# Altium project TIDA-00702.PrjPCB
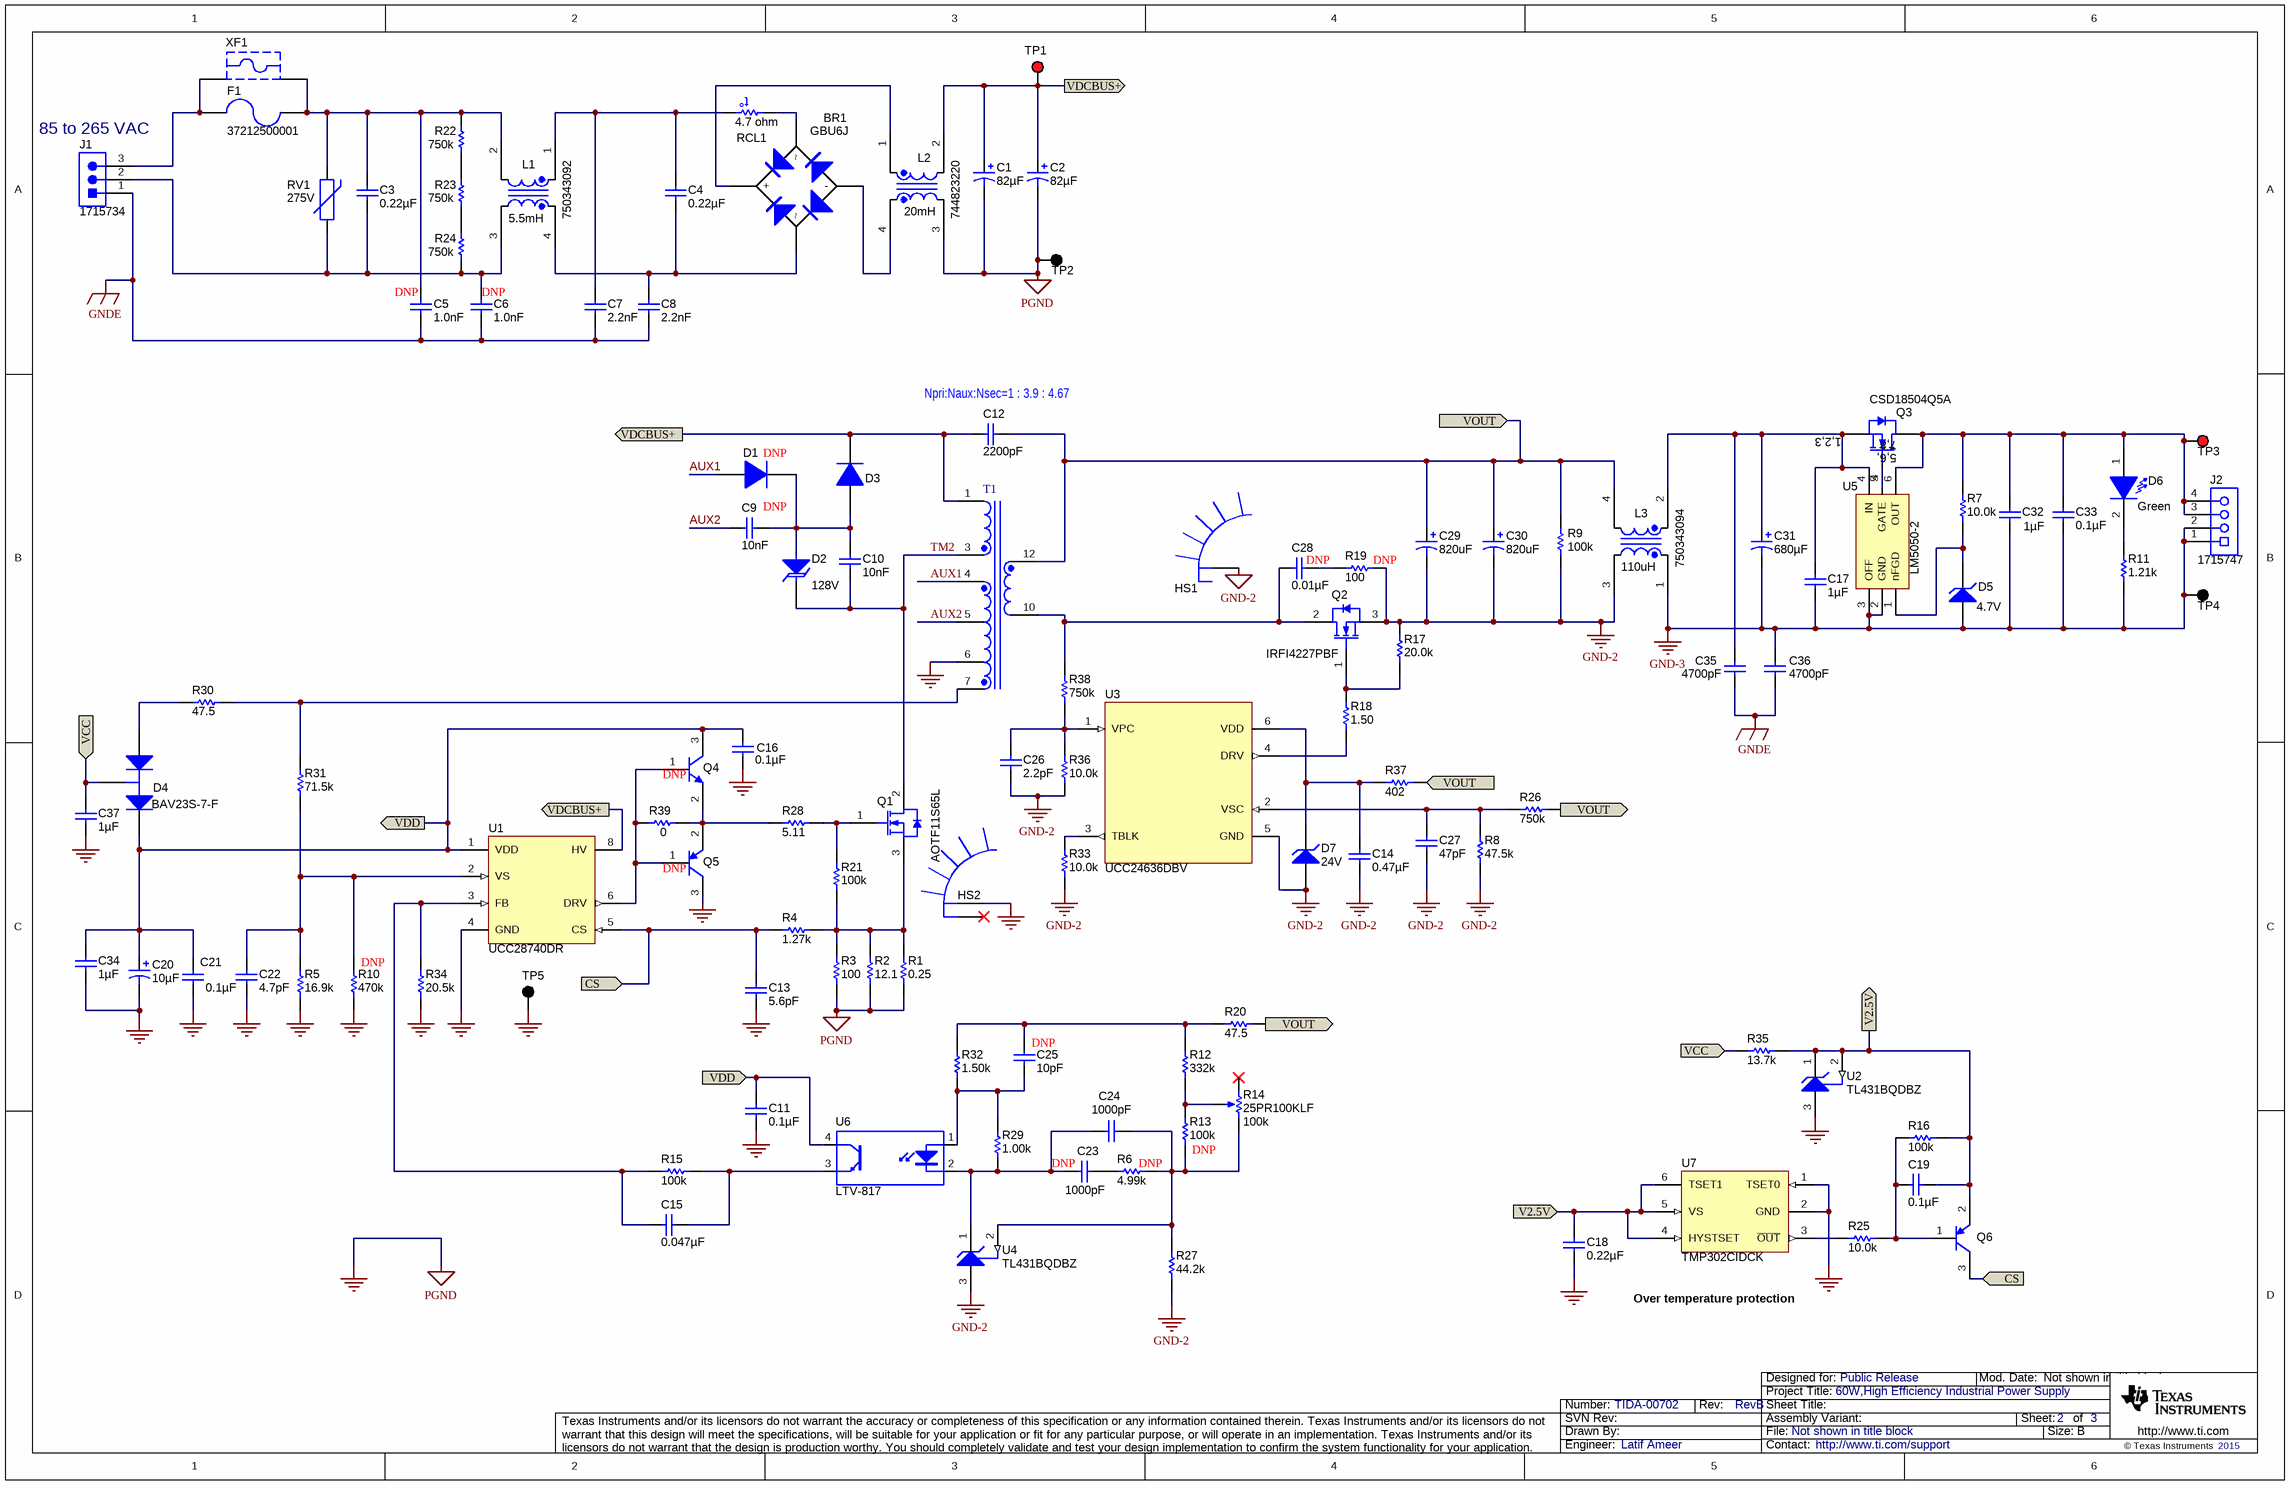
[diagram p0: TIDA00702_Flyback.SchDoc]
CopyrightYear: 2015; PCB_Layout: Manjunatha T N; PCB_Rev: RevB; PRJ_Customer: Public Release; PRJ_Engineer: Latif Ameer; PRJ_Number: TIDA-00702; PRJ_Title: 60W,High Efficiency Industrial Power Supply; SCH_Rev: RevB; TechSupport: http://www.ti.com/support
2 sheets, 137 parts. Net scope: flat (ports and power ports of the same name join across sheets).
Board file: TIDA-00702-RevB.PcbDoc
Sheets:
  TIDA00702_Flyback.SchDoc
  Hardware_ANSI-B.SchDoc

## Sheet TIDA00702_Flyback.SchDoc
size 431 x 279 mm; Date: Not shown in title block; ApprovedBy: Not shown in title block; CheckedBy: Not shown in title block; Author: Not shown in title block; CompanyName: Not shown in title block; Engineer: Not shown in title block; Organization: Not shown in title block; Address1: Not shown in title block; Address2: Not shown in title block; Address3: Not shown in title block; Address4: Not shown in title block; DocumentNumber: 1; Revision: Use project parameter SCH_Rev; SheetNumber: 2; SheetTotal: 3; PageSetup: Record=PageOptions¦CenterHorizontal=True¦CenterVertical=True¦PrintScale=1.00¦XCorrection=1.00¦YCorrection=1.00¦PrintKind=0¦BorderSize=5000000¦LeftOffset=0¦BottomOffset=0¦Orientation=2¦PaperLength=1000¦PaperWidth=1000¦Scale=100¦PaperSource=15¦PrintQuality=600¦MediaType=1¦DitherType=10¦PaperKind=Letter¦PrintScaleMode=1

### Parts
BR1  GBU6J  [GBU]
C1  ValueDisplayed: 82µF  [CAPPRD750W80D1800H3150]  (hidden comment: UCY2W820MHD6)
C2  ValueDisplayed: 82µF  [CAPPRD750W80D1800H3150]  (hidden comment: UCY2W820MHD6)
C3  ValueDisplayed: 0.22µF  [B32922_12.5mm]  (hidden comment: B32922C3224M)
C4  ValueDisplayed: 0.22µF  [B32922_12.5mm]  (hidden comment: B32922C3224M)
C5  ValueDisplayed: 1.0nF  [E_900x700x900]  (hidden comment: C907U102MYVDBA7317)
C6  ValueDisplayed: 1.0nF  [E_900x700x900]  (hidden comment: C907U102MYVDBA7317)
C7  ValueDisplayed: 2.2nF  [E_900x700x900]  (hidden comment: CS80ZU2GA222MYNKA)
C8  ValueDisplayed: 2.2nF  [E_900x700x900]  (hidden comment: CS80ZU2GA222MYNKA)
C9  ValueDisplayed: 10nF  [B32529_450x950x730]  (hidden comment: B32529C8103K)
C10  ValueDisplayed: 10nF  [B32529_450x950x730]  (hidden comment: B32529C8103K)
C11  ValueDisplayed: 0.1µF  [0603]  (hidden comment: C1608X7R1H104K)
C12  ValueDisplayed: 2200pF  [E_900x700x900]  (hidden comment: CS80ZU2GA222MYNKA)
C13  ValueDisplayed: 5.6pF  [0603]  (hidden comment: 06035A5R6CAT2A)
C14  ValueDisplayed: 0.47µF  [0805_HV]  (hidden comment: GRM21BR71H474KA88L)
C15  ValueDisplayed: 0.047µF  [0603]  (hidden comment: C1608X7R1H473K)
C16  ValueDisplayed: 0.1µF  [0603]  (hidden comment: C1608X7R1H104K)
C17  ValueDisplayed: 1µF  [0603]  (hidden comment: GRM188R61H105KAALD)
C18  ValueDisplayed: 0.22µF  [0603]  (hidden comment: C1608X7R1C224K)
C19  ValueDisplayed: 0.1µF  [0603]  (hidden comment: GRM188R61C104KA01D)
C20  ValueDisplayed: 10µF  [FC_400x1100]  (hidden comment: UVR1H100MDD6TP)
C21  ValueDisplayed: 0.1µF  [0603]  (hidden comment: C1608X7R1H104K)
C22  ValueDisplayed: 4.7pF  [0603]  (hidden comment: 06035A4R7CAT2A)
C23  ValueDisplayed: 1000pF  [0603]  (hidden comment: C1608C0G1H102J)
C24  ValueDisplayed: 1000pF  [0603]  (hidden comment: C1608C0G1H102J)
C25  ValueDisplayed: 10pF  [0603]  (hidden comment: 06035A100JAT2A)
C26  ValueDisplayed: 2.2pF  [0603]  (hidden comment: 06035A2R2CAT2A)
C27  ValueDisplayed: 47pF  [0603]  (hidden comment: 06035A470JAT2A)
C28  ValueDisplayed: 0.01µF  [0805_HV]  (hidden comment: C2012X7R2E103K)
C29  ValueDisplayed: 820uF  [CAPPR5-10X20]  (hidden comment: EEU-FR1V821L)
C30  ValueDisplayed: 820uF  [CAPPR5-10X20]  (hidden comment: EEU-FR1V821L)
C31  ValueDisplayed: 680µF  [CAPPR5-10X20]  (hidden comment: EEU-FR1V681)
C32  ValueDisplayed: 1µF  [1206]  (hidden comment: C3216X7R1H105K)
C33  ValueDisplayed: 0.1µF  [1206]  (hidden comment: C1206C104J5RACTU)
C34  ValueDisplayed: 1µF  [1206]  (hidden comment: C3216X7R1H105K)
C35  ValueDisplayed: 4700pF  [CAPRD750W60D750H1050]  (hidden comment: VY2472M49Y5US63V7)
C36  ValueDisplayed: 4700pF  [CAPRD750W60D750H1050]  (hidden comment: VY2472M49Y5US63V7)
C37  ValueDisplayed: 1µF  [1206]  (hidden comment: C3216X7R1H105K)
D1  BYG21M-E3/TR  [SMA]  (value not drawn)
D2  value 128V  [DO-201AD_Vert]  (hidden comment: 1.5KE150A)
D3  BYG21M-E3/TR  [SMA]  (value not drawn)
D4  BAV23S-7-F  [SOT-23]
D5  value 4.7V  [SOD-523]  (hidden comment: BZT52C4V7T-7)
D6  value Green  [LED_HLMP1523]  (hidden comment: HLMP1503)
D7  value 24V  [SOD-123]  (hidden comment: MMSZ5252B-7-F)
F1  37212500001  [FUSE_372]
HS1  V7237C  [HEATSINK_V7237C]  (value not drawn)
HS2  593002B00000G  [HEATSINK_593002B03400G]  (value not drawn)
J1  1715734  [Phoenix_1715734]
J2  1715747  [Phoenix_1715747]
L1  750343092  ValueDisplayed: 5.5mH  [750311982]
L2  744823220  ValueDisplayed: 20mH  [IND_WE-CMB_M]
L3  750343094  ValueDisplayed: 110uH  [IND_750343094]
Q1  AOTF11S65L  [TO-220_FullPAK_Offset]
Q2  IRFI4227PBF  [TO-220AB]
Q3  CSD18504Q5A  [TRANS_NexFET_Q5A]
Q4  MMBT4401WT1G  [SOT-323]  (value not drawn)
Q5  MMBT4403WT1G  [SOT-323]  (value not drawn)
Q6  MMBT4403WT1G  [SOT-323]  (value not drawn)
R1  ValueDisplayed: 0.25  [2010]  (hidden comment: CSRN2010FKR250)
R2  ValueDisplayed: 12.1  [2010]  (hidden comment: CRCW201012R1FKEF)
R3  ValueDisplayed: 100  [1206]  (hidden comment: CRCW1206100RFKEA)
R4  ValueDisplayed: 1.27k  [0603]  (hidden comment: CRCW06031K27FKEA)
R5  ValueDisplayed: 16.9k  [0603]  (hidden comment: CRCW060316K9FKEA)
R6  ValueDisplayed: 4.99k  [0603]  (hidden comment: CRCW06034K99FKEA)
R7  ValueDisplayed: 10.0k  [0603]  (hidden comment: CRCW060310K0FKEA)
R8  ValueDisplayed: 47.5k  [0603]  (hidden comment: CRCW060347K5FKEA)
R9  ValueDisplayed: 100k  [1206]  (hidden comment: CRCW1206100KFKEA)
R10  ValueDisplayed: 470k  [0603]  (hidden comment: RC0603FR-07470KL)
R11  ValueDisplayed: 1.21k  [0603]  (hidden comment: CRCW06031K21FKEA)
R12  ValueDisplayed: 332k  [0603]  (hidden comment: CRCW0603332KFKEA)
R13  ValueDisplayed: 100k  [0603]  (hidden comment: CRCW0603100KFKEA)
R14  25PR100KLF  value 100k  [POT_25PXXXXXX]
R15  ValueDisplayed: 100k  [0603]  (hidden comment: CRCW0603100KFKEA)
R16  ValueDisplayed: 100k  [0603]  (hidden comment: CRCW0603100KFKEA)
R17  ValueDisplayed: 20.0k  [0603]  (hidden comment: CRCW060320K0FKEA)
R18  ValueDisplayed: 1.50  [0603]  (hidden comment: CRCW06031R50FKEA)
R19  ValueDisplayed: 100  [1206]  (hidden comment: CRCW1206100RFKEA)
R20  ValueDisplayed: 47.5  [0603]  (hidden comment: CRCW060347R5FKEA)
R21  ValueDisplayed: 100k  [0603]  (hidden comment: CRCW0603100KFKEA)
R22  ValueDisplayed: 750k  [1206]  (hidden comment: CRCW1206750KFKEA)
R23  ValueDisplayed: 750k  [1206]  (hidden comment: CRCW1206750KFKEA)
R24  ValueDisplayed: 750k  [1206]  (hidden comment: CRCW1206750KFKEA)
R25  ValueDisplayed: 10.0k  [0603]  (hidden comment: CRCW060310K0FKEA)
R26  ValueDisplayed: 750k  [0603]  (hidden comment: CRCW0603750KFKEA)
R27  ValueDisplayed: 44.2k  [0603]  (hidden comment: CRCW060344K2FKEA)
R28  ValueDisplayed: 5.11  [0603]  (hidden comment: CRCW06035R11FKEA)
R29  ValueDisplayed: 1.00k  [0603]  (hidden comment: CRCW06031K00FKEA)
R30  ValueDisplayed: 47.5  [0805_HV]  (hidden comment: CRCW080547R5FKEA)
R31  ValueDisplayed: 71.5k  [0603]  (hidden comment: CRCW060371K5FKEA)
R32  ValueDisplayed: 1.50k  [0603]  (hidden comment: CRCW06031K50FKEA)
R33  ValueDisplayed: 10.0k  [0603]  (hidden comment: CRCW060310K0FKEA)
R34  ValueDisplayed: 20.5k  [0603]  (hidden comment: CRCW060320K5FKEA)
R35  ValueDisplayed: 13.7k  [0603]  (hidden comment: CRCW060313K7FKEA)
R36  ValueDisplayed: 10.0k  [0603]  (hidden comment: CRCW060310K0FKEA)
R37  ValueDisplayed: 402  [0603]  (hidden comment: CRCW0603402RFKEA)
R38  ValueDisplayed: 750k  [0603]  (hidden comment: CRCW0603750KFKEA)
R39  ValueDisplayed: 0  [0603]  (hidden comment: CRCW06030000Z0EA)
RCL1  value 4.7 ohm  [THERM_B57236S0]  (hidden comment: B57236S479M)
RV1  value 275V  [VAR_S10K275E2]  (hidden comment: S10K275E2)
T1  (no value)  [Trans_FBtrans00702]
TP1  5000  [Keystone5000]  (value not drawn)
TP2  5001  [Keystone5001]  (value not drawn)
TP3  5000  [Keystone5000]  (value not drawn)
TP4  5001  [Keystone5001]  (value not drawn)
TP5  5001  [Keystone5001]  (value not drawn)
U1  UCC28740DR  [D0007A_N]
U2  TL431BQDBZ  [DBZ0003A_L]
U3  UCC24636DBV  [DBV0006A_N]
U4  TL431BQDBZ  [DBZ0003A_L]
U5  LM5050-2  [tsop-6]
U6  LTV-817  [DIP762W60P254L460H350Q4B]
U7  TMP302CIDCK  [DCK0006A_N]
XF1  56000001009  [FuseHolder_560000010]  (value not drawn)

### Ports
CS (in), V2.5V (in), V2.5V (out), VCC (in), VDCBUS+, VDD (in), VDD (out), VOUT (in)

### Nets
GND: C1.2(-) C2.2(-) C11.2 C13.2 C16.2 C18.2 C20.2(-) C21.2 C22.2 C34.2 C37.2 HS2.1 L2.3 Q5.3(C) R1.1 R2.2 R3.1 R5.2 R10.1 R34.1 T1.6 TP2.1 TP5.1 U1.4(GND) U2.3(ANODE) U7.1(TSET0) U7.2(GND)  [also labelled PGND]
GND-2: C14.1 C26.2 C27.1 C29.2(-) C30.2(-) D7.2(A) HS1.1 L3.3 Q2.3(S) R8.2 R9.1 R17.2 R19.2 R27.2 R33.2 R36.1 U3.5(GND) U4.3(ANODE)
GND-3: C17.2 C31.2(-) C32.2 C33.2 C36.1 D5.2(A) J2.1 J2.2 L3.1 R11.1 TP4.1 U5.2(GND) U5.3(OFF)
GNDE: C5.2 C6.2 C7.2 C8.2 C35.2 C36.2 J1.1
AUX1: D1.2(A) T1.4
AUX2: C9.2 T1.5
CS: C13.1 Q6.3(C) R4.1 U1.5(CS) ; port CS
TM2: C10.2 D2.1(K) Q1.2(D) T1.3
V2.5V: C18.1 C19.2 Q6.2(E) R16.2 R35.2 U2.1(CATHODE) U2.2(REF) U7.4(HYSTSET) U7.5(VS) U7.6(TSET1) ; port V2.5V
VCC: C37.1 D4.3(C) R35.1 ; port VCC
VDCBUS+: C1.1(+) C2.1(+) C12.1 D3.1(K) L2.2 T1.1 TP1.1 U1.8(HV) ; port VDCBUS+
VDD: C11.1 C16.1 C20.1(+) C21.1 C34.1 D4.2(K) Q4.3(C) U1.1(VDD) U6.4(C) ; port VDD
VOUT: C12.2 C29.1(+) C30.1(+) L3.4 R9.2 R20.1 R26.1 R37.1 T1.12 ; port VOUT
NetBR1_1: BR1.1(+) L2.1
NetBR1_2: BR1.2 C4.2 C8.1 L1.4
NetBR1_3: BR1.3 RCL1.1
NetBR1_4: BR1.4(-) L2.4
NetC3_1: C3.1 C5.1 F1.1 L1.2 R22.1 RV1.2 XF1.1
NetC3_2: C3.2 C6.1 J1.2 L1.3 R24.2 RV1.1
NetC4_1: C4.1 C7.1 L1.1 RCL1.2
NetC9_1: C9.1 C10.1 D1.1(K) D2.2(A) D3.2(A)
NetC14_2: C14.2 D7.1(K) R37.2 U3.6(VDD)
NetC15_1: C15.1 R15.2 R34.2 U1.3(FB)
NetC15_2: C15.2 R15.1 U6.3(E)
NetC17_1: C17.1 C31.1(+) C35.1 L3.2 Q3.1(S) Q3.2(S) Q3.3(S) U5.4(IN)
NetC19_1: C19.1 Q6.1(B) R16.1 R25.2
NetC22_1: C22.1 R5.1 R10.2 R31.1 U1.2(VS)
NetC23_1: C23.1 C24.1 R29.1 U4.1(CATHODE) U6.2(K)
NetC23_2: C23.2 R6.2
NetC24_2: C24.2 R6.1 R13.1 R14.3(CW) R27.1 U4.2(REF)
NetC25_1: C25.1 R12.2 R20.2 R32.1
NetC25_2: C25.2 R29.2 R32.2 U6.1(A)
NetC26_1: C26.1 R36.2 R38.1 U3.1(VPC)
NetC27_2: C27.2 R8.1 R26.2 U3.2(VSC)
NetC28_1: C28.1 R19.1
NetC28_2: C28.2 Q2.2(D) R38.2 T1.10
NetC32_1: C32.1 C33.1 D6.1(A) J2.3 J2.4 Q3.5(D) Q3.6(D) Q3.7(D) Q3.8(D) Q3.9(D) R7.1 TP3.1 U5.6(OUT)
NetD4_1: D4.1(A) R30.2
NetD5_1: D5.1(K) R7.2 U5.1(nFGD)
NetD6_2: D6.2(K) R11.2
NetF1_2: F1.2 J1.3 XF1.2
NetQ1_1: Q1.1(G) R21.2 R28.2
NetQ1_3: Q1.3(S) R1.2 R2.1 R3.2 R4.2 R21.1
NetQ2_1: Q2.1(G) R17.1 R18.2
NetQ3_4: Q3.4(G) U5.5(GATE)
NetQ4_1: Q4.1(B) Q5.1(B) R39.1 U1.6(DRV)
NetQ4_2: Q4.2(E) Q5.2(E) R28.1 R39.2
NetR12_1: R12.1 R13.2 R14.2(WIPER)
NetR18_1: R18.1 U3.4(DRV)
NetR22_2: R22.2 R23.1
NetR23_2: R23.2 R24.1
NetR25_1: R25.1 U7.3(~{OUT})
NetR30_1: R30.1 R31.2 T1.7
NetR33_1: R33.1 U3.3(TBLK)

Not connected (* = marked no-connect by the designer): HS2 2*; R14 1(CCW)*

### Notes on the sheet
- (near J1) 85 to 265 VAC
- (near C5) DNP
- (near C6) DNP
- (near C12) Npri:Naux:Nsec=1 : 3.9 : 4.67
- (near D1) DNP
- (near C9) DNP
- (near C28) DNP
- (near R19) DNP
- (near Q4) DNP
- (near Q5) DNP
- (near R10) DNP
- (near C25) DNP
- (near C23) DNP
- (near R6) DNP
- (near R13) DNP
- Over temperature protection

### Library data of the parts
BR1 = GBU4A-BP: RECT BRIDGE GPP 6A 600V GBU; Manufacturer: Micro Commercial Components; CompType: Diode; U/M: EA; Vf_V: 0.95; Io_A: 4; Vr_V: 50; Value2: 50V; TJmax_C: 150; RJC_CperW: 2.2
C1 C2 = EEUED2E820S: CAP ALUM 82UF 20% 450V RADIAL; Polarized: Y; CompType: Capacitor; U/M: EA; Cap_F: 0.000082; Tolerance_%: 20; VDC_V: 450; IRMS_A: 730mA; TaMin_C: -25; TaMax_C: 105; AC_Derating: 0.3
C3 C4 = B32922C3224M: CAP, Film, 0.22 µF, 630 V, +/- 20%, TH; Manufacturer: TDK; Polarized: N; CompType: Capacitor; Value: 0.22uF; U/M: EA; Cap_F: 0.00000022; Tolerance_%: 20; Value1: Unknown; VDC_V: 630; Value2: 630V; TaMax_C: 110
C5 C6 = DE6E3KJ222MN3A: CAP CER 1000PF 400VAC Y5V RADIAL; Manufacturer: Kemet; Polarized: N; CompType: Capacitor; Value: 1.0nF; U/M: EA; Cap_F: 0.0000000022; Tolerance_%: 20; Value1: Unknown; VDC_V: 300; Value2: 400V; TempCo: E; TaMin_C: -40; TaMax_C: 125
C7 C8 C12 = DE6E3KJ222MN3A: CAP CER 2200PF 300VAC 20% RADIAL; Manufacturer: TDK Corporation; Polarized: N; CompType: Capacitor; Value: 2.2nF; U/M: EA; Cap_F: 0.0000000022; Tolerance_%: 20; Value1: Unknown; VDC_V: 300; Value2: 300V; TempCo: E; TaMin_C: -40; TaMax_C: 125
C9 C10 = B32529C6223J: CAP FILM 10000PF 10% 630VDC RAD; Manufacturer: EPCOS (TDK); Polarized: N; CompType: Capacitor; Value: 10nF; U/M: EA; Tolerance_%: 5; Value1: Unknown; VDC_V: 630; Value2: 630V; TaMin_C: -55; TaMax_C: 125
C11 C16 C21 = C1608X7R1H104K: CAP, CERM, 0.1 µF, 50 V, +/- 10%, X7R, 0603; Manufacturer: TDK; Polarized: N; CompType: Capacitor; Value: 0.1uF; U/M: EA; Cap_F: 0.0000001; Tolerance_%: 10; ESR_ohm: 0.017; Value1: 0.017 ohm; VDC_V: 50; Value2: 50V; TaMin_C: -55; TaMax_C: 125
C13 = 06035A5R6CAT2A: CAP, CERM, 5.6 pF, 50 V, +/- 5%, C0G/NP0, 0603; Manufacturer: AVX; Polarized: N; CompType: Capacitor; Value: 5.6pF; U/M: EA; Cap_F: 0.0000000000056; Tolerance_%: 5; ESR_ohm: 0.568; Value1: 0.568 ohm; VDC_V: 50; Value2: 50V; TaMin_C: -55; TaMax_C: 125
C14 = GRM21BR71H474KA88L: CAP, CERM, 0.47 µF, 50 V, +/- 10%, X7R, 0805; Manufacturer: MuRata; Polarized: N; CompType: Capacitor; Value: 0.47uF; U/M: EA; Cap_F: 0.00000047; Tolerance_%: 10; Value1: Unknown; VDC_V: 50; Value2: 50V; TaMin_C: -55; TaMax_C: 125; Cap_Case: 0805
C15 = C1608X7R1H473K: CAP, CERM, 0.047 µF, 50 V, +/- 10%, X7R, 0603; Manufacturer: TDK; Polarized: N; CompType: Capacitor; Value: 0.047uF; U/M: EA; Cap_F: 0.000000047; Tolerance_%: 10; ESR_ohm: 0.0234; Value1: 0.0234 ohm; VDC_V: 50; Value2: 50V; TaMin_C: -55; TaMax_C: 125
C17 = GRM188R61H105KAALD: CAP, CERM, 1 µF, 50 V, +/- 10%, X5R, 0603; Manufacturer: MuRata; Polarized: N; CompType: Capacitor; Value: 1uF; U/M: EA; Cap_F: 0.000001; Tolerance_%: 10; Value1: Unknown; VDC_V: 50; Value2: 50V; TaMin_C: -55; TaMax_C: 85
C18 = C1608X7R1C224K: CAP, CERM, 0.22 µF, 16 V, +/- 10%, X7R, 0603; Manufacturer: TDK; Polarized: N; CompType: Capacitor; Value: 0.22uF; U/M: EA; Cap_F: 0.00000022; Tolerance_%: 10; ESR_ohm: 0.0125; Value1: 0.0125 ohm; VDC_V: 16; Value2: 16V; TaMin_C: -55; TaMax_C: 125
C19 = GRM188R61C104KA01D: CAP, CERM, 0.1 µF, 16 V, +/- 10%, X5R, 0603; Manufacturer: MuRata; Polarized: N; CompType: Capacitor; Value: 0.1uF; U/M: EA; Cap_F: 0.0000001; Tolerance_%: 10; Value1: Unknown; VDC_V: 16; Value2: 16V; TaMin_C: -55; TaMax_C: 85
C20 = EEU-FC1H100: CAP ALUM 10UF 20% 50V RADIAL; Manufacturer: Nichicon; Polarized: Y; CompType: Capacitor; U/M: EA; Cap_F: 0.00001; Tolerance_%: 20; Value1: 2.5 ohm; VDC_V: 50; ESR_ohm: 2.5; IRMS_A: 0.09; TaMin_C: -55; TaMax_C: 105; Cap_Case: 4.0x11.0
C22 = 06035A4R7CAT2A: CAP, CERM, 4.7 pF, 50 V, +/- 5%, C0G/NP0, 0603; Manufacturer: AVX; Polarized: N; CompType: Capacitor; Value: 4.7pF; U/M: EA; Cap_F: 0.0000000000047; Tolerance_%: 5; ESR_ohm: 0.633; Value1: 0.633 ohm; VDC_V: 50; Value2: 50V; TaMin_C: -55; TaMax_C: 125
C23 C24 = C1608C0G1H102J: CAP, CERM, 1000 pF, 50 V, +/- 5%, C0G/NP0, 0603; Manufacturer: TDK; Polarized: N; CompType: Capacitor; Value: 1000pF; U/M: EA; Cap_F: 0.000000001; Tolerance_%: 5; ESR_ohm: 0.0563; Value1: 0.0563 ohm; VDC_V: 50; Value2: 50V; TaMin_C: -55; TaMax_C: 125
C25 = 06035A100JAT2A: CAP, CERM, 10 pF, 50 V, +/- 5%, C0G/NP0, 0603; Manufacturer: AVX; Polarized: N; CompType: Capacitor; Value: 10pF; U/M: EA; Cap_F: 0.00000000001; Tolerance_%: 5; ESR_ohm: 0.403; Value1: 0.403 ohm; VDC_V: 50; Value2: 50V; TaMin_C: -55; TaMax_C: 125
C26 = 06035A2R2CAT2A: CAP, CERM, 2.2 pF, 50 V, +/- 11%, C0G/NP0, 0603; Manufacturer: AVX; Polarized: N; CompType: Capacitor; Value: 2.2pF; U/M: EA; Cap_F: 0.0000000000022; Tolerance_%: 11; ESR_ohm: 1.033; Value1: 1.033 ohm; VDC_V: 50; Value2: 50V; TaMin_C: -55; TaMax_C: 125
C27 = 06035A470JAT2A: CAP, CERM, 47 pF, 50 V, +/- 5%, C0G/NP0, 0603; Manufacturer: AVX; Polarized: N; CompType: Capacitor; Value: 47pF; U/M: EA; Cap_F: 0.000000000047; Tolerance_%: 5; ESR_ohm: 0.174; Value1: 0.174 ohm; VDC_V: 50; Value2: 50V; TaMin_C: -55; TaMax_C: 125
C28 = C2012X7R2E103K: CAP, CERM, 0.01 µF, 250 V, +/- 10%, X7R, 0805; Manufacturer: TDK; Polarized: N; CompType: Capacitor; Value: 0.01uF; U/M: EA; Cap_F: 0.00000001; Tolerance_%: 10; ESR_ohm: 0.0681; Value1: 0.0681 ohm; VDC_V: 250; Value2: 250V; TaMin_C: -55; TaMax_C: 125; Cap_Case: 0805
C29 C30 = EEU-FR1V681: CAP ALUM 820UF 20% 35V RADIAL; Manufacturer: Panasonic; Polarized: Y; CompType: Capacitor; U/M: EA; Cap_F: 0.00082; Tolerance_%: 20; Value1: Unknown; VDC_V: 35; IRMS_A: 2.47; TaMin_C: -40; TaMax_C: 105; Cap_Case: 10x27
C31 = EEU-FR1V681: CAP, AL, 680 µF, 35 V, +/- 20%, TH; Manufacturer: Panasonic; Polarized: Y; CompType: Capacitor; Value: 680uF; U/M: EA; Cap_F: 0.00068; Tolerance_%: 20; Value1: Unknown; VDC_V: 35; Value2: 35V; IRMS_A: 2.47; TaMin_C: -40; TaMax_C: 105; Cap_Case: 10x20
C32 C34 C37 = C3216X7R1H105K: CAP, CERM, 1 µF, 50 V, +/- 10%, X7R, 1206; Manufacturer: TDK; Polarized: N; CompType: Capacitor; Value: 1uF; U/M: EA; Cap_F: 0.000001; Tolerance_%: 10; ESR_ohm: 0.01; Value1: 0.01 ohm; VDC_V: 50; Value2: 50V; IRMS_A: 3.2; TaMin_C: -55; TaMax_C: 125
C33 = C1206C104J5RACTU: CAP, CERM, 0.1 µF, 50 V, +/- 5%, X7R, 1206; Manufacturer: Kemet; Polarized: N; CompType: Capacitor; Value: 0.1uF; U/M: EA; Cap_F: 0.0000001; Tolerance_%: 5; ESR_ohm: 0.059; Value1: 0.059 ohm; VDC_V: 50; Value2: 50V; IRMS_A: 1.2; TaMin_C: -55; TaMax_C: 125
C35 C36 = VY2102M29Y5UG63V7: CAP CER 4700PF 440VAC Y5U RADIAL; Manufacturer: Vishay-Bccomponents; Polarized: N; CompType: Capacitor; U/M: EA; Tolerance_%: 20; Value1: Unknown; Value2: 300; TaMin_C: -40; TaMax_C: 125; Cap_Case: Radial Disc 7.5mm, ls=7.5; AEC Category: Q200
D1 D3 = BYG21M-E3/TR: Diode, Fast Rectifier, 1000 V, 1.5 A, SMA; Manufacturer: Vishay-Semiconductor; U/M: EA; Vf_V: 1.6; Value: 1000V; Value1: 1.5A; Value2: 1.6V; Io_A: 1.5; Vr_V: 1000; TJmax_C: 150
D2 = SMCJ100A: TVS DIODE 128VWM 207VC AXIAL; Manufacturer: Littelfuse; U/M: EA; Power_W: 1500; Vr_V: 100; Value1: 1500W; RJA_CperW: 75
D4 = BAV23S-7-F: Diode, Switching, 200 V, 0.4 A, SOT-23; Manufacturer: Diodes Inc.; U/M: EA; Vf_V: 1.25; Value: 200V; Value1: 0.4A; Value2: 1.25V; Io_A: 0.4; Vr_V: 200; TJmax_C: 150; RJC_CperW: 357
D5 = BZT52C4V7T-7: Diode, Zener, 4.7 V, 300 mW, SOD-523; Manufacturer: Diodes Inc.; U/M: EA; SymbolCreator: a0412235; Power_W: 0.3; Vz_V: 4.7; Value1: 0.3W; RJA_CperW: 417
D6 = HLMP1523: LED SS HI EFF GREEN DIFF 3MM; Manufacturer: Everlight; Vf_V: 2.2; Value2: 2.2V; Io_A: 0.02; Tjmax_C: 100; Value1: W; U/M: EA
D7 = MMSZ5252B-7-F: Diode, Zener, 24V, 500mW, SOD-123; Manufacturer: Diodes Inc.; SymbolCreator: a0412235; U/M: EA; Power_W: 0.5; Vz_V: 24; Value1: 0.5W; RJA_CperW: 350
F1 = 37212500001: Fuse, 2.5 A, 250 V, TH; Manufacturer: Littelfuse; U/M: EA; OpeningTime_200%_max: 2; VDC_V: 250; Irating_A: 2.5; Vdrop: 0.08; Soldering_Wave_MaxTemp_C: 260; Soldering_Wave_MaxTime_s: 5
HS1 = 593002B00000G: HEATSINK TO-220 19.05X13.21MM; Manufacturer: Assmann WSW Components; SymbolCreator: a0799628; Value: 21.0°C/W
HS2 = 593002B00000G: HEATSINK TWISTED FIN TO-220 Vertical; Manufacturer: Aavid Thermalloy; SymbolCreator: a0799628; Value: 13.4°C/W
J1 = 1715734: TERM BLOCK 3POS 5.08MM, TH; Manufacturer: Phoenix Contact; SymbolCreator: a0799628; CompType: Header; U/M: EA
J2 = 1715747: Terminal Block, 5.08mm, 4x1, TH; Manufacturer: Phoenix Contact; SymbolCreator: a0411947; U/M: EA
L1 = 744823210: Coupled inductor, 7mH, 2 A, 0.045 ohm,+/-32%; Manufacturer: Wurth Elektronik; SymbolCreator: a0412235; Value: 5.5mH; Ind_H: 5.5e-3; DCR_ohm: 0.045
L2 = 744823210: Coupled inductor, 20 mH, 1.5A, 0.270 ohm, +/- 30%, TH; Manufacturer: Wurth Elektronik; SymbolCreator: a0412235; Value: 20mH; Ind_H: 20.0E-3; DCR_ohm: 0.270; Tolerance_%: 30
L3 = 744823210: Coupled inductor, 7mH, 2 A, 0.045 ohm, 3.7-7.1 mH; Manufacturer: Wurth Elektronik; SymbolCreator: a0412235; Value: 100uH; DCR_ohm: 0.045; Isat: 2; Tolerance_%: 30
Q1 = IPP50R199CP: MOSFET N-CH 650V 11A TO220F; Manufacturer: Alpha & Omega Semiconductor Inc.; Alternate Manufacturer: None; U/M: EA; ChType: N; VdsMax_V: 650; Value1: 399 mohm; Rdson45_ohm: 0; Value2: 13.2nC; QgTyp_nC: 34; Vgs_V: 20
Q2 = IRFB4410ZPBF: MOSFET N-CH 200V 26A TO-220FP; Manufacturer: International Rectifier; Alternate Manufacturer: None; U/M: EA; ChType: N; VdsMax_V: 200; Value1: 25 mOhm @ 17A, 10V; Value2: 100 nC; QgTyp_nC: 100nC at 10V; Vgs_V: 20; IdsMax_A: 97
Q3 = CSD18504Q5A: MOSFET, N-CH, 40 V, 15 A, SON 5x6mm; Manufacturer: Texas Instruments; Alternate Manufacturer: None; U/M: EA; ChType: N; Value: 40V; VdsMax_V: 40; Value1: 0.0098 ohm; Rdson45_ohm: 0.0098; Value2: 7.7 nC; QgTyp_nC: 7.7; Vgs_V: 20; IdsMax_A: 15
Q4 = CMST2222A TR, Central Semiconductor: Transistor, NPN, 40 V, 0.6 A, SOT-323; Manufacturer: ON Semiconductor; CompType: BJT; PNP: 0; NPN: 1; Vceo_V: 40; Vcesat1_V: 0.3; Value: 40 V; IcRated_A: 0.6; Value1: 0.6 A; TaMin_C: -65; TaMax_C: 150; U/M: EA
Q5 = MMBT2907A, Fairchild Semiconductor: Transistor, PNP, 40 V, 0.6 A, SOT-323; Manufacturer: ON Semiconductor; CompType: BJT; PNP: 1; NPN: 0; Vceo_V: 40; Vcesat1_V: 0.75; Value: 40 V; IcRated_A: 0.8; Value1: 0.6 A; HfeMax: 300; TaMin_C: -55; TaMax_C: 150; U/M: EA
Q6 = MMBT2907A, Fairchild Semiconductor: Transistor, PNP, 40 V, 0.6 A, SOT-323; CompType: BJT; PNP: 1; NPN: 0; Vceo_V: 40; Vcesat1_V: 0.75; Value: 40 V; IcRated_A: 0.8; Value1: 0.6 A; HfeMax: 300; TaMin_C: -55; TaMax_C: 150; U/M: EA
R1 = CSRN2010FKR250: RES, 0.25, 1%, 1 W, 2010; Manufacturer: Stackpole Electronics Inc; CompType: Resistor; Value: 0.25; Value_Code: R250; Tolerance_%: 1; Value2: 1W; TempCo: 250 ppm/C; U/M: EA
R2 = CRCW201012R1FKEF: RES, 12.1, 1%, 0.75 W, 2010; Manufacturer: Vishay-Dale; CompType: Resistor; Value: 12.1; Value_Code: 12R1; Tolerance_%: 1; Power_W: 0.75; Value2: 0.75W; VDC_V: 400; TempCo: 100 ppm/C; EIA_Code: E96; U/M: EA
R3 R19 = CRCW1206100RFKEA: RES, 100, 1%, 0.25 W, 1206; Manufacturer: Vishay-Dale; CompType: Resistor; Value: 100; Value_Code: 100R; Tolerance_%: 1; Power_W: 0.25; Value2: 0.25W; VDC_V: 200; TempCo: 100 ppm/C; EIA_Code: E96; U/M: EA
R4 = CRCW06031K27FKEA: RES, 1.27 k, 1%, 0.1 W, 0603; Manufacturer: Vishay-Dale; CompType: Resistor; Value: 1.27k; Res_ohm: 1270; Value_Code: 1k27; Tolerance_%: 1; Power_W: 0.1; Value2: 0.1W; VDC_V: 75; TempCo: 100 ppm/C; EIA_Code: E96; U/M: EA
R5 = CRCW060316K9FKEA: RES, 16.9 k, 1%, 0.1 W, 0603; Manufacturer: Vishay-Dale; CompType: Resistor; Value: 16.9k; Res_ohm: 16900; Value_Code: 16k9; Tolerance_%: 1; Power_W: 0.1; Value2: 0.1W; VDC_V: 75; TempCo: 100 ppm/C; EIA_Code: E96; U/M: EA
R6 = CRCW06034K99FKEA: RES, 4.99 k, 1%, 0.1 W, 0603; Manufacturer: Vishay-Dale; CompType: Resistor; Value: 4.99k; Res_ohm: 4990; Value_Code: 4k99; Tolerance_%: 1; Power_W: 0.1; Value2: 0.1W; VDC_V: 75; TempCo: 100 ppm/C; EIA_Code: E96; U/M: EA
R7 = CRCW060310K0FKEA: RES, 10.0 k, 1%, 0.1 W, 0603; Manufacturer: Vishay-Dale; CompType: Resistor; Value: 10.0k; U/M: EA; Res_ohm: 10000; Value_Code: 10k0; Tolerance_%: 1; Power_W: 0.1; Value2: 0.1W; VDC_V: 75; TempCo: 100 ppm/C; EIA_Code: E96
R8 = CRCW060347K5FKEA: RES, 47.5 k, 1%, 0.1 W, 0603; Manufacturer: Vishay-Dale; CompType: Resistor; Value: 47.5k; Res_ohm: 47500; Value_Code: 47k5; Tolerance_%: 1; Power_W: 0.1; Value2: 0.1W; VDC_V: 75; TempCo: 100 ppm/C; EIA_Code: E96; U/M: EA
R9 = CRCW1206100KFKEA: RES, 100 k, 1%, 0.25 W, 1206; Manufacturer: Vishay-Dale; CompType: Resistor; Value: 100k; Res_ohm: 100000; Tolerance_%: 1; Power_W: 0.25; Value2: 0.25W; VDC_V: 200; TempCo: 100 ppm/C; EIA_Code: E96; U/M: EA
R10 = RC0603FR-07470KL: RES, 470 k, 1%, 0.1 W, 0603; Manufacturer: Yageo America; CompType: Resistor; Value: 470k; Res_ohm: 470000; Tolerance_%: 1; Power_W: 0.1; Value2: 0.1W; VDC_V: 150; TempCo: 200 ppm/C; U/M: EA
R11 = CRCW06031K21FKEA: RES, 1.21 k, 1%, 0.1 W, 0603; Manufacturer: Vishay-Dale; CompType: Resistor; Value: 1.21k; Res_ohm: 1210; Value_Code: 1k21; Tolerance_%: 1; Power_W: 0.1; Value2: 0.1W; VDC_V: 75; TempCo: 100 ppm/C; EIA_Code: E96; U/M: EA; AEC Category: Q200
R12 = CRCW0603332KFKEA: RES, 332 k, 1%, 0.1 W, 0603; Manufacturer: Vishay-Dale; CompType: Resistor; Value: 332k; Res_ohm: 332000; Tolerance_%: 1; Power_W: 0.1; Value2: 0.1W; VDC_V: 75; TempCo: 100 ppm/C; EIA_Code: E96; U/M: EA
R13 R15 R16 R21 = CRCW0603100KFKEA: RES, 100 k, 1%, 0.1 W, 0603; Manufacturer: Vishay-Dale; CompType: Resistor; Value: 100k; Res_ohm: 100000; Tolerance_%: 1; Power_W: 0.1; Value2: 0.1W; VDC_V: 75; TempCo: 100 ppm/C; EIA_Code: E96; U/M: EA
R14 = 3266W-1-203LF: TRIMMER 100K OHM 0.5W TH; Manufacturer: TT Electronics/BI; Sim Note: Enter the Resistance value and the set point into parameter fields.
R17 = CRCW060320K0FKEA: RES, 20.0 k, 1%, 0.1 W, 0603; Manufacturer: Vishay-Dale; CompType: Resistor; Value: 20.0k; Res_ohm: 20000; Value_Code: 20k0; Tolerance_%: 1; Power_W: 0.1; Value2: 0.1W; VDC_V: 75; TempCo: 100 ppm/C; EIA_Code: E96; U/M: EA
R18 = CRCW06031R50FKEA: RES, 1.50, 1%, 0.1 W, 0603; Manufacturer: Vishay-Dale; CompType: Resistor; Value: 1.50; Res_ohm: 1.5; Value_Code: 1R50; Tolerance_%: 1; Power_W: 0.1; Value2: 0.1W; VDC_V: 75; TempCo: 100 ppm/C; EIA_Code: E96; U/M: EA
R20 = CRCW060347R5FKEA: RES, 47.5, 1%, 0.1 W, 0603; Manufacturer: Vishay-Dale; CompType: Resistor; Value: 47.5; Value_Code: 47R5; Tolerance_%: 1; Power_W: 0.1; Value2: 0.1W; VDC_V: 75; TempCo: 100 ppm/C; EIA_Code: E96; U/M: EA
R22-R24 = CRCW1206750KFKEA: RES, 750 k, 1%, 0.25 W, 1206; Manufacturer: Vishay-Dale; Value: 750k; CompType: Resistor; Res_ohm: 750000; Tolerance_%: 1; Power_W: 0.25; Value2: 0.25W; VDC_V: 200; TempCo: 100 ppm/C; EIA_Code: E96; U/M: EA
R25 R33 R36 = CRCW060310K0FKEA: RES, 10.0 k, 1%, 0.1 W, 0603; Manufacturer: Vishay-Dale; CompType: Resistor; Value: 10.0k; Res_ohm: 10000; Value_Code: 10k0; Tolerance_%: 1; Power_W: 0.1; Value2: 0.1W; VDC_V: 75; TempCo: 100 ppm/C; EIA_Code: E96; U/M: EA
R26 R38 = CRCW0603750KFKEA: RES, 750 k, 1%, 0.1 W, 0603; Manufacturer: Vishay-Dale; CompType: Resistor; Value: 750k; Res_ohm: 750000; Tolerance_%: 1; Power_W: 0.1; Value2: 0.1W; VDC_V: 75; TempCo: 100 ppm/C; EIA_Code: E96; U/M: EA
R27 = CRCW060344K2FKEA: RES, 44.2 k, 1%, 0.1 W, 0603; Manufacturer: Vishay-Dale; CompType: Resistor; Value: 44.2k; Res_ohm: 44200; Value_Code: 44k2; Tolerance_%: 1; Power_W: 0.1; Value2: 0.1W; VDC_V: 75; TempCo: 100 ppm/C; EIA_Code: E96; U/M: EA
R28 = CRCW06035R11FKEA: RES, 5.11, 1%, 0.1 W, 0603; Manufacturer: Vishay-Dale; CompType: Resistor; Value: 5.11; Value_Code: 5R11; Tolerance_%: 1; Power_W: 0.1; Value2: 0.1W; VDC_V: 75; TempCo: 100 ppm/C; EIA_Code: E96; U/M: EA; AEC Category: Q200
R29 = CRCW06031K00FKEA: RES, 1.00 k, 1%, 0.1 W, 0603; Manufacturer: Vishay-Dale; CompType: Resistor; Value: 1.00k; Res_ohm: 1000; Value_Code: 1k00; Tolerance_%: 1; Power_W: 0.1; Value2: 0.1W; VDC_V: 75; TempCo: 100 ppm/C; EIA_Code: E96; U/M: EA
R30 = CRCW080547R5FKEA: RES, 47.5, 1%, 0.125 W, 0805; Manufacturer: Vishay-Dale; CompType: Resistor; Value: 47.5; Value_Code: 47R5; Tolerance_%: 1; Power_W: 0.125; Value2: 0.125W; VDC_V: 150; TempCo: 100 ppm/C; EIA_Code: E96; U/M: EA
R31 = CRCW060371K5FKEA: RES, 71.5 k, 1%, 0.1 W, 0603; Manufacturer: Vishay-Dale; CompType: Resistor; Value: 71.5k; Res_ohm: 71500; Value_Code: 71k5; Tolerance_%: 1; Power_W: 0.1; Value2: 0.1W; VDC_V: 75; TempCo: 100 ppm/C; EIA_Code: E96; U/M: EA
R32 = CRCW06031K50FKEA: RES, 1.50 k, 1%, 0.1 W, 0603; Manufacturer: Vishay-Dale; CompType: Resistor; Value: 1.50k; Res_ohm: 1500; Value_Code: 1k50; Tolerance_%: 1; Power_W: 0.1; Value2: 0.1W; VDC_V: 75; TempCo: 100 ppm/C; EIA_Code: E96; U/M: EA
R34 = CRCW060320K5FKEA: RES, 20.5 k, 1%, 0.1 W, 0603; Manufacturer: Vishay-Dale; CompType: Resistor; Value: 20.5k; Res_ohm: 20500; Value_Code: 20k5; Tolerance_%: 1; Power_W: 0.1; Value2: 0.1W; VDC_V: 75; TempCo: 100 ppm/C; EIA_Code: E96; U/M: EA
R35 = CRCW060313K7FKEA: RES, 13.7 k, 1%, 0.1 W, 0603; Manufacturer: Vishay-Dale; CompType: Resistor; Value: 13.7k; Res_ohm: 13700; Value_Code: 13k7; Tolerance_%: 1; Power_W: 0.1; Value2: 0.1W; VDC_V: 75; TempCo: 100 ppm/C; EIA_Code: E96; U/M: EA
R37 = CRCW0603402RFKEA: RES, 402, 1%, 0.1 W, 0603; Manufacturer: Vishay-Dale; CompType: Resistor; Value: 402; Value_Code: 402R; Tolerance_%: 1; Power_W: 0.1; Value2: 0.1W; VDC_V: 75; TempCo: 100 ppm/C; EIA_Code: E96; U/M: EA
R39 = CRCW06030000Z0EA: RES, 0, 5%, 0.1 W, 0603; Manufacturer: Vishay-Dale; CompType: Resistor; Value: 0; Value_Code: 0000; Tolerance_%: 5; Power_W: 0.1; Value2: 0.1W; VDC_V: 75; TempCo: 200 ppm/C; EIA_Code: E24; U/M: EA; AEC Category: Q200
RCL1 = B57236S0100M000: ICL 4.7 OHM 20% 4.6A 11.51MM; Manufacturer: EPCOS (TDK); CompType: ThermistorNTC; Tolerance_%: 20; Power_W: 2.1; U/M: EA; TaMin_C: -55; TaMax_C: 170
RV1 = S10K275E2: Varistor 275V RMS 10MM Radial, TH; Manufacturer: EPCOS Inc; SymbolCreator: a0412235
T1 = 750314722: Transformer, 230uH, SMT; Manufacturer: Wurth Elektronik; SymbolCreator: x0208326; DCR_Ohm: 6.05; Value: 8mH; U/M: EA
TP1 TP3 = 5000: Test Point, Miniature, Red, TH; Manufacturer: Keystone; CompType: Test Point Loop; U/M: EA
TP2 TP4 TP5 = 5001: Test Point, Miniature, Black, TH; Manufacturer: Keystone; CompType: Test Point Loop; U/M: EA
U1 = UCC28740DR: Constant-Voltage, Constant-Current Flyback Controller Using Opto-Coupler Feedback, D0007A; Manufacturer: Texas Instruments; SymbolCreator: a0412235; CompType: IC; U/M: EA
U2 U4 = TL431BQDBZ: Precision VREF Shunt Adjustable; Alternate Manufacturer: Texas Instruments; SymbolCreator: a0412235; CompType: IC; U/M: EA
U3 = UCC24630DBV: Sync. Rectifier Controller; Manufacturer: Texas Instruments; SymbolCreator: a0411947; CompType: IC; U/M: EA
U5 = LM5050-2: High Side OR-ING FET Controller; Manufacturer: Texas Instruments; SymbolVersion: use current date i.e. 2008-05-20; SymbolCreator: Use LDAP id; CompType: Used in some BOM reports.  Useful for finding later.; U/M: EA, IN, or GM
U6 = LTV-817: Optocoupler, 5 kV, 50-600% CTR, TH-4; Manufacturer: Lite-On; U/M: EA; CTR_Min: 50% @ 5mA; CTR_Max: 600% @ 5mA; Voltage_Isolation_Vrms: 5000; tr_typ: 4us; tf_typ: 3us
U7 = TMP300BIDCK: Low-Power,  Low-Supply  Temperature  Switch; Alternate Manufacturer: None; Manufacturer: Texas Instruments; SymbolCreator: a0412235; CompType: IC; U/M: EA
XF1 = 56000001009: FUSE HOLDER RADIAL 250V 6.3A PCB; Manufacturer: Littelfuse; SymbolCreator: a0412235; Value: TR5

## Sheet Hardware_ANSI-B.SchDoc
size 431 x 279 mm; Date: Not shown in title block; ApprovedBy: Not shown in title block; CheckedBy: Not shown in title block; Author: Not shown in title block; CompanyName: Not shown in title block; Engineer: Not shown in title block; Organization: Not shown in title block; Address1: Not shown in title block; Address2: Not shown in title block; Address3: Not shown in title block; Address4: Not shown in title block; DocumentNumber: 1; Revision: Use project parameter SCH_Rev; SheetNumber: 3; SheetTotal: 3; PageSetup: Record=PageOptions¦CenterHorizontal=True¦CenterVertical=True¦PrintScale=1.00¦XCorrection=1.00¦YCorrection=1.00¦PrintKind=0¦BorderSize=5000000¦LeftOffset=0¦BottomOffset=0¦Orientation=2¦PaperLength=1000¦PaperWidth=1000¦Scale=100¦PaperSource=15¦PrintQuality=600¦MediaType=1¦DitherType=10¦PaperKind=Letter¦PrintScaleMode=1
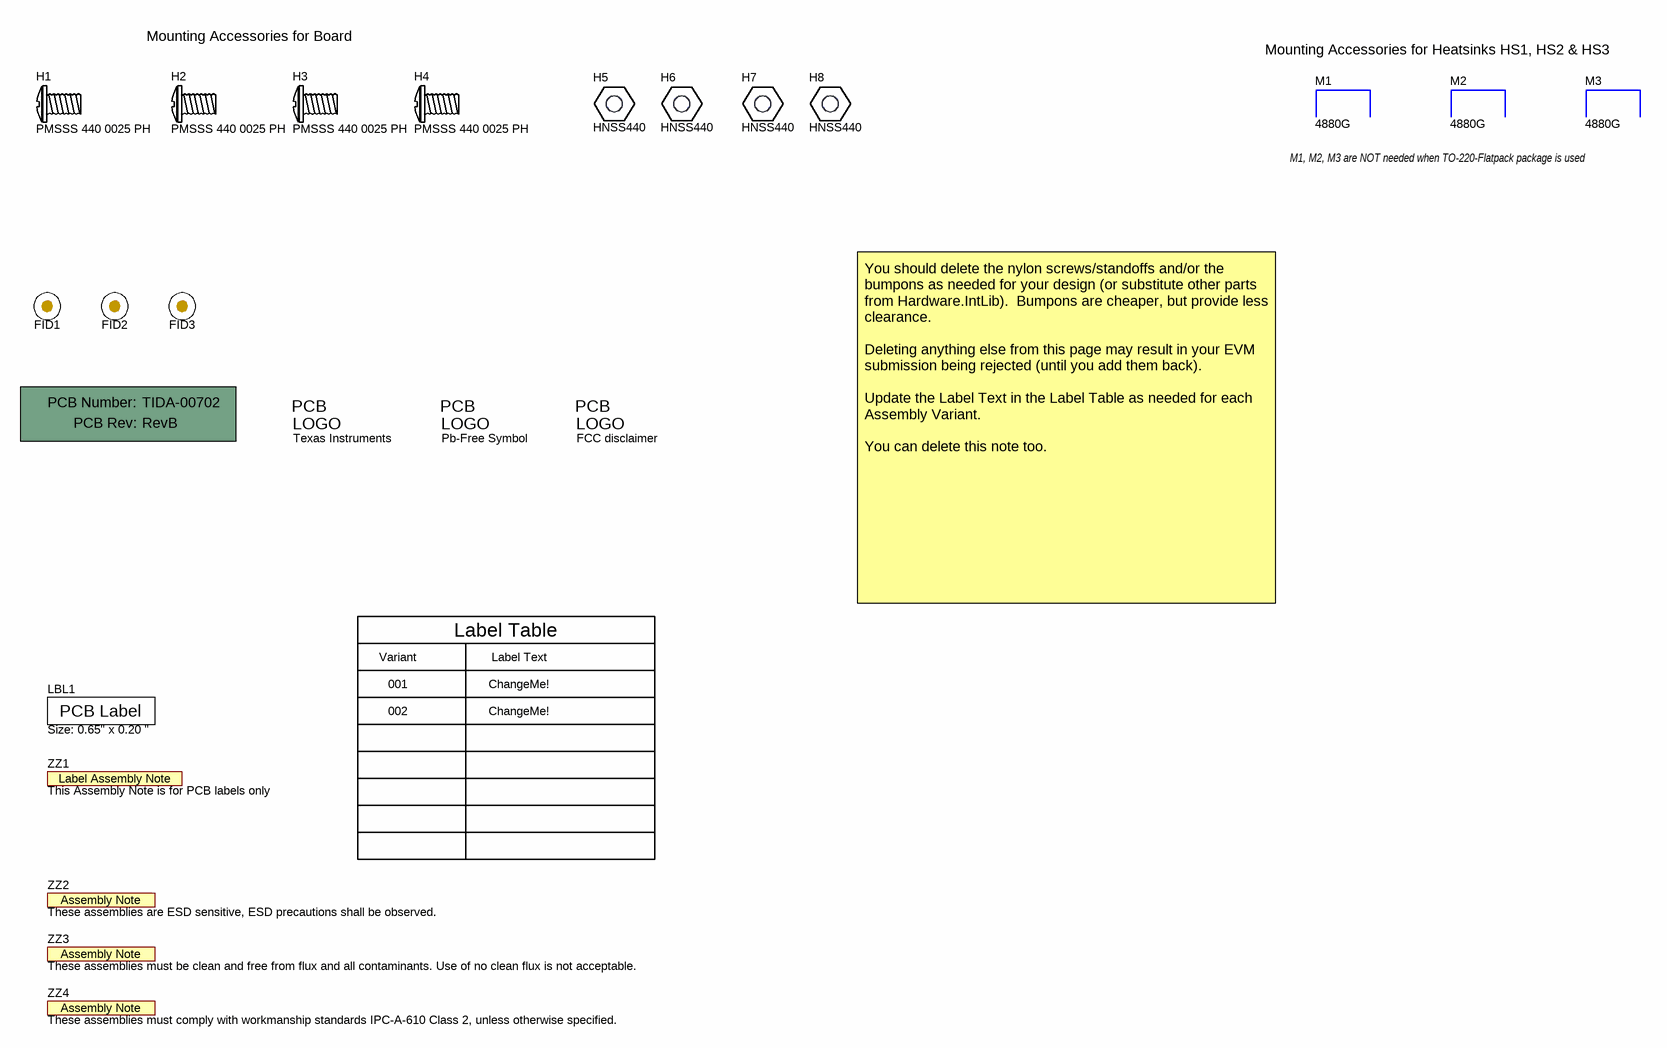
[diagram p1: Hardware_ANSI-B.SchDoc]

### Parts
!PCB1  Printed Circuit Board  (value not drawn)  (mechanical)
FID1  Fiducial  [Fiducial10-20]  (value not drawn)
FID2  Fiducial  [Fiducial10-20]  (value not drawn)
FID3  Fiducial  [Fiducial10-20]  (value not drawn)
H1  PMSSS 440 0025 PH  [B_F_PMSSS4400025PH]
H2  PMSSS 440 0025 PH  [B_F_PMSSS4400025PH]
H3  PMSSS 440 0025 PH  [B_F_PMSSS4400025PH]
H4  PMSSS 440 0025 PH  [B_F_PMSSS4400025PH]
H5  HNSS440
H6  HNSS440
H7  HNSS440
H8  HNSS440
LBL1  Size: 0.65" x 0.20 "  [Label_650x200]
Logo1  Texas Instruments  [TI_STACKED_OVERLAY_SMALL]  (no BOM)
Logo2  Pb-Free Symbol  [Pb-Free_Overlay_Small]  (no BOM)
Logo3  FCC disclaimer  [FCC_disclaimer]  (no BOM)
M1  4880G
M2  4880G
M3  4880G
ZZ1  This Assembly Note is for PCB labels only  [AssemblyNoteLabel]  (no BOM)
ZZ2  These assemblies are ESD sensitive, ESD precautions shall be observed.  [AssemblyNote]  (no BOM)
ZZ3  These assemblies must be clean and free from flux and all contaminants. Use of no clean flux is not acceptable.  [AssemblyNote]  (no BOM)
ZZ4  These assemblies must comply with workmanship standards IPC-A-610 Class 2, unless otherwise specified.  [AssemblyNote]  (no BOM)

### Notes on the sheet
- Mounting Accessories for Board
- Mounting Accessories for Heatsinks HS1, HS2 & HS3
- M1, M2, M3 are NOT needed when TO-220-Flatpack package is used
- Variant
- Label Table
- Label Text
- You should delete the nylon screws/standoffs and/or the bumpons as needed for your design (or substitute other parts from Hardware.IntLib).  Bumpons are cheaper, but provide less clearance.
  Deleting anything else from this page may result in your EVM submission being rejected (until you add them back).
  Update the Label Text in the Label Table as needed for each Assembly Variant.
  You can delete this note too.
- 001
- 002
- ChangeMe!

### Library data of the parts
!PCB1 = PCB: Manufacturer: Any; PartNumber: TIDA-00702; SymbolCreator: a0412235
FID1-FID3 = Fiducial: Fiducial mark.  There is nothing to buy or mount.; SymbolCreator: codlsc
H1-H4 = PMSSS 440 0025 PH: MACHINE SCREW PAN PHILLIPS 4-40; Manufacturer: B&F Fastener Supply; SymbolCreator: a0412235; CompType: Standoff
H5-H8 = SMTSO-440-2ET: HEX NUT 1/4" STN STEEL 4-40; Manufacturer: B&F Fastener Supply; SymbolCreator: a0412235; CompType: Hardware
LBL1 = THT-14-423-10: Thermal Transfer Printable Labels, 0.650" W x 0.200" H - 10,000 per roll; Manufacturer: Brady; SymbolCreator: a0412235; CompType: Label
Logo1 = TI_Logo: Texas Instrument Corporate Signature; SymbolCreator: a0412235
Logo2 = Pb-Free: SymbolCreator: a0412235
Logo3 = FCC_disclaimer: SymbolCreator: codlsc
M1-M3 = PCC-SMP-CLIP: MOUNTING KIT TO-220; Manufacturer: Aavid Thermalloy; SymbolCreator: Altium; CompType: Hardware
ZZ1 = AssemblyNoteLabel: SymbolCreator: a0412235
ZZ2-ZZ4 = AssemblyNote: SymbolCreator: codlsc

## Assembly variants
001: not fitted C5 C6 C9 C23 C25 C28 D1 Q4 Q5 R6 R10 R13 R19
Variant of TIDA-00702: all parts fitted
